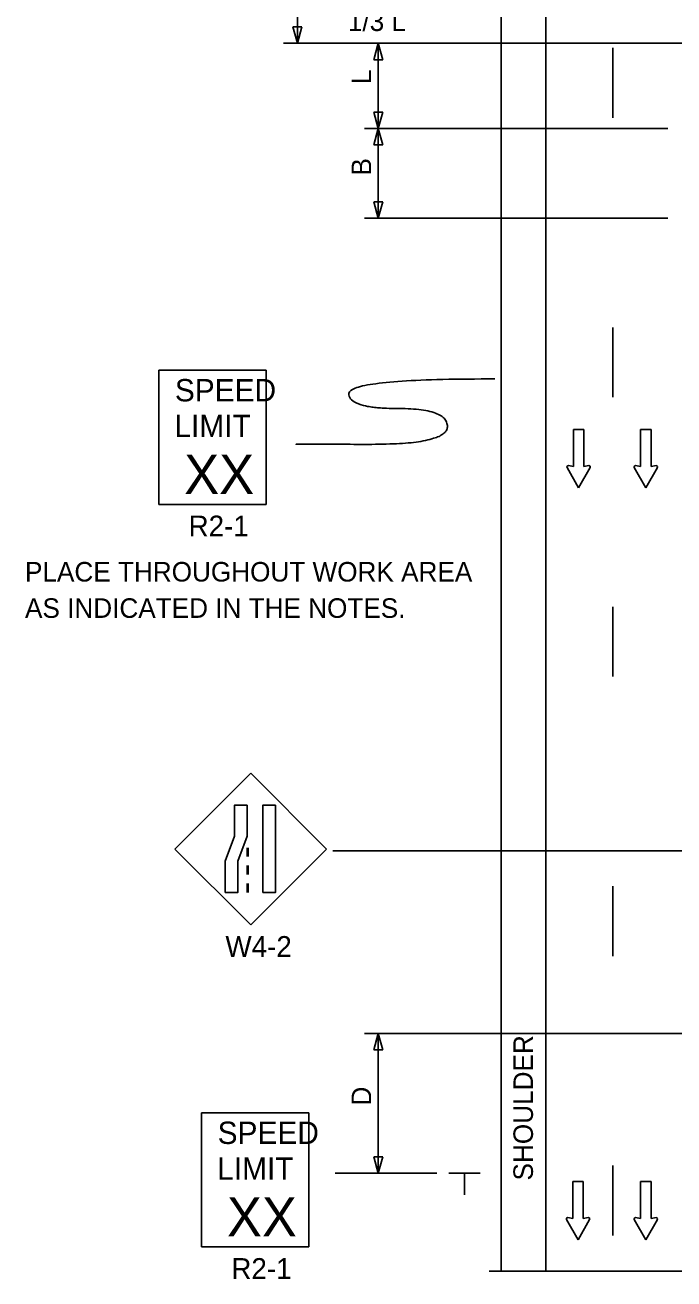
# Model space of a CAD drawing. Extents: x 16730 to 19504, y 5662 to 6979.
# Drawn here: x 16747.3 to 16979.7, y 6098.3 to 6547 of the extents above; entities that cross this region are included whole.
import ezdxf

# ---------------------------------------------------------------- set-up
doc = ezdxf.new("R2010")
doc.units = 0
for name, color, linetype in [('ALI_LEGAL_EX', 7, 'Continuous'), ('MT_SCRATCH_LEVEL_E', 7, 'Continuous'), ('PAVT_EDGE_EX', 7, 'Continuous'), ('TRAFFIC_SIGNS_PR', 7, 'Continuous'), ('TYPICAL_TEXT_DIMEN_PR', 7, 'Continuous')]:
    doc.layers.add(name, color=color, linetype=linetype)

msp = doc.modelspace()

# ---------------------------------------------------------------- linework, layer by layer
at = {"layer": 'ALI_LEGAL_EX'}
for points in [[(16957.81, 6513.81), (16957.81, 6538.81)], [(16957.81, 6413.81), (16957.81, 6438.81)], [(16957.81, 6313.81), (16957.81, 6338.81)], [(16957.81, 6213.81), (16957.81, 6238.81)], [(16957.81, 6113.81), (16957.81, 6138.81)]]:
    msp.add_lwpolyline(points, dxfattribs=at)
at = {"layer": 'MT_SCRATCH_LEVEL_E'}
for p, q in [((16947.41, 6402.27), (16943.67, 6402.27)), ((16943.67, 6402.27), (16943.67, 6389.02)), ((16947.41, 6402.27), (16943.67, 6402.27)), ((16943.67, 6402.27), (16943.67, 6389.02)), ((16947.41, 6389.02), (16947.41, 6402.27)), ((16947.41, 6389.02), (16947.41, 6402.27)), ((16971.48, 6402.27), (16967.74, 6402.27)), ((16967.74, 6402.27), (16967.74, 6389.02)), ((16971.48, 6402.27), (16967.74, 6402.27)), ((16967.74, 6402.27), (16967.74, 6389.02)), ((16971.48, 6389.02), (16971.48, 6402.27)), ((16971.48, 6389.02), (16971.48, 6402.27)), ((16941.41, 6388.65), (16945.56, 6381.41)), ((16941.41, 6388.65), (16945.56, 6381.41)), ((16943.67, 6389.02), (16941.89, 6389.33)), ((16943.67, 6389.02), (16941.89, 6389.33)), ((16945.56, 6381.41), (16949.67, 6388.65)), ((16945.56, 6381.41), (16949.67, 6388.65)), ((16949.19, 6389.33), (16947.41, 6389.02)), ((16949.19, 6389.33), (16947.41, 6389.02)), ((16965.48, 6388.65), (16969.63, 6381.41)), ((16965.48, 6388.65), (16969.63, 6381.41)), ((16967.74, 6389.02), (16965.96, 6389.33)), ((16967.74, 6389.02), (16965.96, 6389.33)), ((16969.63, 6381.41), (16973.74, 6388.65)), ((16969.63, 6381.41), (16973.74, 6388.65)), ((16973.26, 6389.33), (16971.48, 6389.02)), ((16973.26, 6389.33), (16971.48, 6389.02)), ((16947.22, 6133.16), (16943.48, 6133.16)), ((16943.48, 6133.16), (16943.48, 6119.9)), ((16947.22, 6133.16), (16943.48, 6133.16)), ((16943.48, 6133.16), (16943.48, 6119.9)), ((16947.22, 6119.9), (16947.22, 6133.16)), ((16947.22, 6119.9), (16947.22, 6133.16)), ((16971.48, 6133.16), (16967.74, 6133.16)), ((16967.74, 6133.16), (16967.74, 6119.9)), ((16971.48, 6133.16), (16967.74, 6133.16)), ((16967.74, 6133.16), (16967.74, 6119.9)), ((16971.48, 6119.9), (16971.48, 6133.16)), ((16971.48, 6119.9), (16971.48, 6133.16)), ((16941.23, 6119.53), (16945.37, 6112.29)), ((16941.23, 6119.53), (16945.37, 6112.29)), ((16943.48, 6119.9), (16941.71, 6120.22)), ((16943.48, 6119.9), (16941.71, 6120.22)), ((16945.37, 6112.29), (16949.48, 6119.53)), ((16945.37, 6112.29), (16949.48, 6119.53)), ((16949, 6120.22), (16947.22, 6119.9)), ((16949, 6120.22), (16947.22, 6119.9)), ((16965.48, 6119.53), (16969.63, 6112.29)), ((16965.48, 6119.53), (16969.63, 6112.29)), ((16967.74, 6119.9), (16965.96, 6120.22)), ((16967.74, 6119.9), (16965.96, 6120.22)), ((16969.63, 6112.29), (16973.74, 6119.53)), ((16969.63, 6112.29), (16973.74, 6119.53)), ((16973.26, 6120.22), (16971.48, 6119.9)), ((16973.26, 6120.22), (16971.48, 6119.9))]:
    msp.add_line(p, q, dxfattribs=at)
for centre, start, end in [((16941.82, 6388.87), 80.0362, 209.7731), ((16941.82, 6388.87), 80.0362, 209.7731), ((16949.26, 6388.87), 330.4248, 99.9638), ((16949.26, 6388.87), 330.4248, 99.9638), ((16965.89, 6388.87), 80.0362, 209.7731), ((16965.89, 6388.87), 80.0362, 209.7731), ((16973.33, 6388.87), 330.4248, 99.9638), ((16973.33, 6388.87), 330.4248, 99.9638), ((16941.64, 6119.76), 80.0362, 209.7731), ((16941.64, 6119.76), 80.0362, 209.7731), ((16949.08, 6119.76), 330.4248, 99.9638), ((16949.08, 6119.76), 330.4248, 99.9638), ((16965.89, 6119.76), 80.0362, 209.7731), ((16965.89, 6119.76), 80.0362, 209.7731), ((16973.33, 6119.76), 330.4248, 99.9638), ((16973.33, 6119.76), 330.4248, 99.9638)]:
    msp.add_arc(centre, 0.463, start, end, dxfattribs=at)
at = {"layer": 'PAVT_EDGE_EX'}
for p, q in [((16917.81, 6869.88), (16917.81, 6101.02)), ((16933.81, 6869.88), (16933.81, 6101.02))]:
    msp.add_line(p, q, dxfattribs=at)
at = {"layer": 'TRAFFIC_SIGNS_PR'}
for p, q in [((16795.19, 6423.46), (16833.59, 6423.46)), ((16795.19, 6375.46), (16795.19, 6423.46)), ((16833.59, 6375.46), (16833.59, 6423.46)), ((16795.19, 6375.46), (16833.59, 6375.46)), ((16828.1, 6279.26), (16800.95, 6252.11)), ((16855.25, 6252.11), (16828.1, 6279.26)), ((16800.95, 6252.11), (16828.1, 6224.96)), ((16826.85, 6252.6), (16826.85, 6249.4)), ((16827.25, 6252.6), (16827.25, 6249.4)), ((16828.1, 6224.96), (16855.25, 6252.11)), ((16826.85, 6246.2), (16826.85, 6243)), ((16827.25, 6246.2), (16827.25, 6243)), ((16826.85, 6239.8), (16826.85, 6236.6)), ((16827.25, 6239.8), (16827.25, 6236.6)), ((16810.49, 6157.71), (16848.9, 6157.71)), ((16810.49, 6109.71), (16810.49, 6157.71)), ((16848.9, 6109.71), (16848.9, 6157.71)), ((16810.49, 6109.71), (16848.9, 6109.71))]:
    msp.add_line(p, q, dxfattribs=at)
for points in [[(16826.85, 6267.85), (16826.85, 6256.67), (16823.51, 6247.78), (16823.51, 6236.6), (16819.02, 6236.6), (16819.02, 6247.78), (16822.36, 6256.67), (16822.36, 6267.85)], [(16836.99, 6267.85), (16836.99, 6236.6), (16832.5, 6236.6), (16832.5, 6267.85)]]:
    msp.add_lwpolyline(points, close=True, dxfattribs=at)
at = {"layer": 'TYPICAL_TEXT_DIMEN_PR'}
for p, q in [((16844.82, 6590.47), (16844.82, 6540.47)), ((16844.82, 6540.47), (16843.25, 6546.33)), ((16843.25, 6546.33), (16844.82, 6546.33)), ((16844.82, 6546.33), (16846.39, 6546.33)), ((16846.39, 6546.33), (16844.82, 6540.47)), ((16839.82, 6540.47), (17000.57, 6540.47)), ((16872.24, 6534.6), (16873.81, 6540.47)), ((16873.81, 6540.47), (16875.38, 6534.6)), ((16873.81, 6540.47), (16873.81, 6509.94)), ((16873.81, 6534.6), (16872.24, 6534.6)), ((16875.38, 6534.6), (16873.81, 6534.6)), ((16873.81, 6509.94), (16872.24, 6515.8)), ((16872.24, 6515.8), (16873.81, 6515.8)), ((16873.81, 6515.8), (16875.38, 6515.8)), ((16875.38, 6515.8), (16873.81, 6509.94)), ((16868.81, 6509.94), (16977.55, 6509.94)), ((16872.24, 6504.08), (16873.81, 6509.94)), ((16873.81, 6509.94), (16873.81, 6477.88)), ((16873.81, 6509.94), (16875.38, 6504.08)), ((16873.81, 6504.08), (16872.24, 6504.08)), ((16875.38, 6504.08), (16873.81, 6504.08)), ((16873.81, 6477.88), (16872.24, 6483.74)), ((16872.24, 6483.74), (16873.81, 6483.74)), ((16873.81, 6483.74), (16875.38, 6483.74)), ((16875.38, 6483.74), (16873.81, 6477.88)), ((16868.81, 6477.88), (16977.55, 6477.88)), ((17031.52, 6251.52), (16857.53, 6251.52)), ((16996.51, 6186.1), (16868.81, 6186.1)), ((16872.24, 6180.24), (16873.81, 6186.1)), ((16873.81, 6186.1), (16873.81, 6136.1)), ((16873.81, 6186.1), (16875.38, 6180.24)), ((16873.81, 6180.24), (16872.24, 6180.24)), ((16875.38, 6180.24), (16873.81, 6180.24)), ((16873.81, 6136.1), (16872.24, 6141.96)), ((16872.24, 6141.96), (16873.81, 6141.96)), ((16873.81, 6141.96), (16875.38, 6141.96)), ((16875.38, 6141.96), (16873.81, 6136.1)), ((16858.39, 6136.1), (16894.81, 6136.1)), ((16899.06, 6136.1), (16910.31, 6136.1)), ((16904.69, 6136.1), (16904.69, 6128.32)), ((16913.51, 6101.02), (17122.11, 6101.02))]:
    msp.add_line(p, q, dxfattribs=at)
msp.add_open_spline([(16915.54, 6420.38), (16863.24, 6420.38), (16863.24, 6409.77), (16898.57, 6409.77), (16898.57, 6396.96), (16844.39, 6396.96), (16844.39, 6396.96)], degree=2, dxfattribs=at)

# ---------------------------------------------------------------- texts
at = {"layer": 'TRAFFIC_SIGNS_PR'}
for s, height, p in [('SPEED', 8, (16800.95, 6412.32)), ('LIMIT', 8, (16800.79, 6399.52)), ('XX', 14.031, (16804.3, 6379.22)), ('R2-1', 7.44, (16805.86, 6364.02)), ('PLACE THROUGHOUT WORK AREA', 7, (16747.28, 6347.85)), ('AS INDICATED IN THE NOTES.', 7, (16747.28, 6334.85)), ('W4-2', 7.44, (16819.06, 6213.52)), ('SPEED', 8, (16816.26, 6146.57)), ('LIMIT', 8, (16816.1, 6133.77)), ('XX', 14.031, (16819.61, 6113.47)), ('R2-1', 7.44, (16821.17, 6098.27))]:
    msp.add_text(s, height=height, dxfattribs=at).set_placement(p)
at = {"layer": 'TYPICAL_TEXT_DIMEN_PR'}
msp.add_text('1/3 L', height=7, dxfattribs=at).set_placement((16862.91, 6544.87))
for s, p in [('L', (16871.25, 6525.85)), ('B', (16871.25, 6493.15)), ('SHOULDER', (16929.19, 6133.49)), ('D', (16871.25, 6160.32))]:
    msp.add_text(s, height=7, rotation=90, dxfattribs=at).set_placement(p)

doc.saveas('drawing.dxf')
